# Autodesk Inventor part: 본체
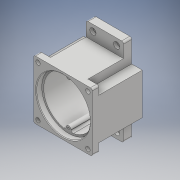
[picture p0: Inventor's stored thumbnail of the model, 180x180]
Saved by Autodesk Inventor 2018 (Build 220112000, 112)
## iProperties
Created: 2020-07
Part Number: 본체
Material: 일반
Document SubType Name: Modeling
Designer: Admin
Density: 1 g/cm^3
Appearance: 기본값
Author: Admin
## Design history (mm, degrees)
sketch "스케치1"
  geometry: L1 (65.8, 0)-(-65.8, 0) reference; L2 (0, -65.8)-(0, 65.8) reference; L3 (47, -47)-(-47, -47); L4 (-47, -47)-(-47, 47); L5 (-47, 47)-(47, 47); L6 (47, 47)-(47, -47); L7 (47, -47)-(-47, 47); L8 (-47, -47)-(47, 47); 1 further point
  constraints: 12 end point, 2 midpoint, 2 parallel, 1 horizontal, 1 perpendicular
  dimensions: "d0" = 94 distance of L4.end L5.end; "d1" = 94 distance of L3.end L4.end
extrude "돌출1" new body sketch "스케치1" distance "d2" = 10; taper "d3" = 0 deg
sketch "스케치2"
  geometry: L1 (-65.8, 0)-(65.8, 0) reference; L2 (0, 65.8)-(0, -65.8) reference; L3 (47, -33)-(-47, -33); L4 (-47, -33)-(-47, 33); L5 (-47, 33)-(47, 33); L6 (47, 33)-(47, -33); L7 (47, -33)-(-47, 33); L8 (-47, -33)-(47, 33); 1 further point
  constraints: 12 end point, 2 midpoint, 2 parallel, 1 horizontal, 1 perpendicular
  dimensions: "d4" = 94 distance of L4.end L5.end; "d5" = 66 distance of L3.end L4.end
extrude "돌출2" join sketch "스케치2" distance "d6" = 57; taper "d7" = 0 deg
sketch "스케치3"
  geometry: L1 (-47, -33)-(47, -33) reference; L2 (47, -33)-(47, 33) reference; L3 (47, 33)-(-47, 33) reference; L4 (-47, 33)-(-47, -33) reference; L5 (-65.8, 0)-(65.8, 0) reference; L6 (0, 98)-(0, -98) reference; L7 (30, -70)-(-30, -70); L8 (-30, -70)-(-30, 70); L9 (-30, 70)-(30, 70); L10 (30, 70)-(30, -70); L11 (30, -70)-(-30, 70); L12 (-30, -70)-(30, 70); L13 (-30, -70)-(30, -70); L14 (-30, 70)-(30, 70); L15 (47, -33)-(47, 33) reference; L16 (47, -33)-(47, 33); L17 (-47, -33)-(-47, 33); L18 (47, -33)-(-47, -33) reference; L19 (-47, -33)-(-30, -33); L20 (-30, -70)-(-30, -33); L21 (-47, 33)-(47, 33) reference; L22 (-47, 33)-(-30, 33); L23 (-30, 33)-(-30, 70); L24 (30, -70)-(30, -33); L25 (30, -33)-(47, -33); L26 (30, 33)-(47, 33); L27 (30, 33)-(30, 70); 1 further point
  constraints: 36 end point, 9 point on line, 7 collinear, 2 midpoint, 2 parallel, 1 horizontal, 1 perpendicular, 1 vertical
  dimensions: "d8" = 60 distance of L8.end L9.end; "d9" = 140 distance of L7.end L8.end
extrude "돌출3" join sketch "스케치3" distance "d10" = 13; taper "d11" = 0 deg
sketch "스케치4"
  geometry: L1 (-47, -33)-(-30, -33) reference; L2 (-30, -33)-(-30, -70) reference; L3 (-30, -70)-(30, -70) reference; L4 (30, -70)-(30, -33) reference; L5 (30, -33)-(47, -33) reference; L6 (47, -33)-(47, 33) reference; L7 (47, 33)-(30, 33) reference; L8 (30, 33)-(30, 70) reference; L9 (30, 70)-(-30, 70) reference; L10 (-30, 70)-(-30, 33) reference; L11 (-30, 33)-(-47, 33) reference; L12 (-47, 33)-(-47, -33) reference; L13 (-65.8, 0)-(65.8, 0) reference; L14 (0, 98)-(0, -98) reference; C1 r 27.5 at (-11, 0); 1 further point
  constraints: 1 centre point, 1 point on line
  dimensions: "d12" = 55 diameter of C1; "d13" = 11 distance of point (0, 0) C1.centre
extrude "돌출4" join sketch "스케치4" distance "d14" = 7; taper "d15" = 0 deg
sketch "스케치5"
  geometry: C1 r 27.5 at (0, 0) reference; C2 r 16 at (0, 0); 1 further point
  constraints: 1 centre point, 1 coincident
  dimensions: "d16" = 32 diameter of C2
extrude "돌출5" cut sketch "스케치5" distance "d17" = 8.3; taper "d18" = 0 deg
sketch "스케치6"
  geometry: C1 r 16 at (0, 0) reference; C2 r 12.5 at (0, 0); 1 further point
  constraints: 1 centre point, 1 coincident
  dimensions: "d19" = 25 diameter of C2
extrude "돌출6" cut sketch "스케치6" distance "d20" = 4.7; taper "d21" = 0 deg
sketch "스케치7"
  geometry: C1 r 12.5 at (0, 0) reference; C2 r 17.5 at (0, 0); 1 further point
  constraints: 1 centre point, 1 coincident
  dimensions: "d22" = 35 diameter of C2
extrude "돌출7" cut sketch "스케치7" distance "d23" = 10; taper "d24" = 0 deg
sketch "스케치8"
  geometry: L1 (-47, -47)-(47, -47) reference; L2 (47, -47)-(47, 47) reference; L3 (47, 47)-(-47, 47) reference; L4 (-47, 47)-(-47, -47) reference; L5 (-65.8, 0)-(65.8, 0) reference; L6 (0, -98)-(0, 98) reference; C1 r 43 at (0, 0); 1 further point
  constraints: 1 centre point, 1 coincident
  dimensions: "d25" = 86 diameter of C1
extrude "돌출8" cut sketch "스케치8" distance "d26" = 9; taper "d27" = 0 deg
sketch "스케치9"
  geometry: L1 (-65.8, 0)-(65.8, 0) reference; L2 (0, -98)-(0, 98) reference; C1 r 43 at (0, 0) reference; C2 r 40 at (0, 0); 1 further point
  constraints: 1 centre point, 1 coincident
  dimensions: "d28" = 80 diameter of C2
sketch "스케치10"
  geometry: L1 (-47, 47)-(47, 47) reference; L2 (-47, -47)-(-47, 47) reference; L3 (47, 47)-(47, -47) reference; L4 (47, -47)-(-47, -47) reference; L5 (-65.8, 0)-(65.8, 0) reference; L6 (0, 98)-(0, -98) reference; L7 (-30, 47)-(30, 47); L8 (-30, 47)-(-30, 33); L9 (-30, 33)-(30, 33); L10 (30, 33)-(30, 47); L11 (-30, -47)-(-30, -33); L12 (-30, -33)-(30, -33); L13 (-30, -47)-(30, -47); L14 (30, -33)-(30, -47); 1 further point
  constraints: 16 end point, 5 symmetric about line, 3 perpendicular, 2 point on line
  dimensions: "d29" = 60 distance of L7.start L7.end; "d30" = 14 distance of L7.start L8.end
extrude "돌출9" join sketch "스케치10" stored distance "d31" = 55; taper "d32" = 0 deg
extrude "돌출10" cut sketch "스케치9" distance "d33" = 55; taper "d34" = 0 deg
sketch "스케치11"
  geometry: L1 (-65.8, 0)-(65.8, 0) reference; L2 (0, -98)-(0, 98) reference; C1 r 17.5 at (-11, 0) reference; C2 r 17.5 at (-11, 0) reference; C3 r 40 at (0, 0); A1 r 21 centre (-11, 0) between (7.984, 8.978) and (7.984, -8.978); A2 r 15 centre (20, 0) between (7.984, 8.978) and (7.984, -8.978); A3 r 21 centre (-11, 0) between (7.984, 8.978) and (7.984, -8.978); A4 r 15 centre (20, 0) between (7.984, -8.978) and (7.984, 8.978); 1 further point
  constraints: 8 point on circle, 5 centre point, 4 coincident, 1 point on line
  dimensions: "d35" = 42 diameter of A1; "d36" = 30 diameter of A2; "d37" = 20 distance from line of A2.centre L2; "d38" = 80 diameter of C3
extrude "돌출11" cut sketch "스케치11" distance "d39" = 7; taper "d40" = 0 deg
sketch "스케치12"
  geometry: L1 (-65.8, 0)-(65.8, 0) reference; L2 (0, -98)-(0, 98) reference; C1 r 17.5 at (-11, 0) reference; C2 r 11 at (20, 0); A1 r 15 centre (20, 0) between (7.984, -8.978) and (7.984, 8.978) reference; A2 r 21 centre (-11, 0) between (7.984, 8.978) and (7.984, -8.978) reference; 1 further point
  constraints: 1 centre point, 1 coincident
  dimensions: "d41" = 22 diameter of C2
extrude "돌출12" cut sketch "스케치12" distance "d42" = 7; taper "d43" = 0 deg
sketch "스케치13"
  geometry: C1 r 11 at (0, 0) reference; C2 r 9.5 at (0, 0); 1 further point
  constraints: 1 centre point, 1 coincident
  dimensions: "d44" = 19 diameter of C2
extrude "돌출13" cut sketch "스케치13" distance "d45" = 3; taper "d46" = 0 deg
sketch "스케치14"
  geometry: L1 (-65.8, 0)-(65.8, 0) reference; L2 (0, -98)-(0, 98) reference; L3 (-3.994, 35.778)-(-3.994, 41.932); L4 (3.994, 35.778)-(3.994, 41.932); L5 (3.994, 41.932)-(-3.994, 41.932); L6 (-3.994, 35.778)-(-3.994, 42.814); L7 (3.994, 35.778)-(3.994, 42.814); L8 (-3.994, -35.778)-(-3.994, -42.814); L9 (3.994, -35.778)-(3.994, -42.814); C1 r 40 at (0, 0) reference; A1 r 43 centre (0, 0) between (-3.994, 42.814) and (3.994, 42.814) reference; A2 r 36 centre (0, 0) between (0, 36) and (-3.994, 35.778); A3 r 4 centre (0, 36) between (-3.994, 35.778) and (3.994, 35.778); A4 r 4 centre (0, 36) between (-3.994, 35.778) and (3.994, 35.778); A5 r 43 centre (0, 0) between (3.994, 42.814) and (-3.994, 42.814); A6 r 43 centre (0, 0) between (-3.994, -42.814) and (3.994, -42.814); A7 r 4 centre (0, -36) between (3.994, -35.778) and (-3.994, -35.778); 1 further point
  constraints: 15 point on circle, 14 end point, 6 centre point, 5 symmetric about line, 3 coincident, 3 point on line, 2 vertical, 1 perpendicular, 2 other
  dimensions: "d47" = 72 diameter of A2; "d48" = 8 diameter of A3
extrude "돌출14" join sketch "스케치14" stored distance "d49" = 3; taper "d50" = 0 deg
sketch "스케치15"
  geometry: L1 (-47, -47)-(47, -47) reference; L2 (47, -47)-(47, 47) reference; L3 (47, 47)-(-47, 47) reference; L4 (-47, 47)-(-47, -47) reference; L5 (-65.8, 0)-(65.8, 0) reference; L6 (0, -98)-(0, 98) reference; L7 (40, -40)-(-40, -40); L8 (-40, -40)-(-40, 40); L9 (-40, 40)-(40, 40); L10 (40, 40)-(40, -40); L11 (40, -40)-(-40, 40); L12 (-40, -40)-(40, 40); C1 r 43 at (0, 0) reference; 5 further points
  constraints: 12 end point, 4 coincident, 2 midpoint, 2 parallel, 1 horizontal, 1 perpendicular
  dimensions: "d51" = 80 distance of L8.end L9.end; "d52" = 80 distance of L7.end L8.end
hole "구멍1" sketch "스케치15" at (-40, -40), (-40, 40), (40, 40), (40, -40) diameter "d53" = 7; stored, may be unused: countersink angle "d57" = 90 deg, drill point angle "d59" = 118 deg; dims "d54" = 6, "d55" = 4, "d56" = 2, "d58" = 10
sketch "스케치16"
  geometry: L1 (-65.8, 0)-(65.8, 0) reference; L2 (0, -98)-(0, 98) reference; L3 (19, -60)-(-19, -60); L4 (-19, -60)-(-19, 60); L5 (-19, 60)-(19, 60); L6 (19, 60)-(19, -60); L7 (19, -60)-(-19, 60); L8 (-19, -60)-(19, 60); 5 further points
  constraints: 12 end point, 4 coincident, 2 midpoint, 2 parallel, 1 horizontal, 1 perpendicular
  dimensions: "d60" = 38 distance of L4.end L5.end; "d61" = 120 distance of L3.end L4.end
hole "구멍2" sketch "스케치16" at (-19, 60), (19, 60), (-19, -60), (19, -60) diameter "d62" = 4.5; stored, may be unused: countersink angle "d66" = 90 deg, drill point angle "d68" = 118 deg; dims "d63" = 6, "d64" = 10, "d65" = 5, "d67" = 13
sketch "스케치17"
  geometry: L1 (94, 0)-(0, 0) reference; L2 (94, 0)-(94, 10) reference; L3 (80, 10)-(94, 10) reference; L4 (80, 10)-(80, 80) reference; L5 (14, 80)-(80, 80) reference; L6 (14, 10)-(14, 80) reference; L7 (0, 10)-(14, 10) reference; L8 (0, 0)-(0, 10) reference; L9 (47, -17.4)-(47, 104.4) reference; L10 (-51, 0)-(145, 0) reference; 2 further points
  constraints: 1 other
  dimensions: "d69" = 40 distance from line of L1 point (47, 40)
feature "엠보싱1" sketch "스케치17" dims "d70" = 0.5, "d71" = 0
sketch "스케치18"
  geometry: L1 (3.994, -39.8)-(3.994, -35.778) reference; L2 (-3.994, -35.778)-(-3.994, -39.8) reference; L3 (-3.994, 39.8)-(-3.994, 35.778) reference; L4 (3.994, 35.778)-(3.994, 39.8) reference; C1 r 43 at (0, 0) reference; A1 r 40 centre (0, 0) between (3.994, -39.8) and (3.994, 39.8) reference; A2 r 4 centre (0, -36) between (3.994, -35.778) and (-3.994, -35.778) reference; A3 r 40 centre (0, 0) between (-3.994, 39.8) and (-3.994, -39.8) reference; A4 r 4 centre (0, 36) between (-3.994, 35.778) and (3.994, 35.778) reference; 3 further points
  constraints: 2 coincident
hole "구멍3" sketch "스케치18" at (0, -36), (0, 36) diameter "d72" = 3.242; stored, may be unused: countersink angle "d76" = 90 deg, drill point angle "d78" = 118 deg; dims "d73" = 7, "d74" = 10, "d75" = 5, "d77" = 9
chamfer "모따기1" distance "d79" = 0.8; stored, may be unused: second distance "d80" = 2, angle "d81" = 30 deg
chamfer "모따기2" distance "d82" = 1; stored, may be unused: second distance "d83" = 2, angle "d84" = 45 deg
chamfer "모따기3" distance "d85" = 1; stored, may be unused: second distance "d86" = 2, angle "d87" = 45 deg
fillet "모깎기1" dims "d88" = 3
node "솔리드1"
node "투영된 루프1"
node "투영된 루프2"
node "투영된 루프3"
node "투영된 루프4"
node "투영된 루프5"
node "투영된 루프6"
node "투영된 루프7"
node "투영된 루프8"
node "투영된 루프9"
node "투영된 루프10"
node "투영된 루프11"
node "투영된 루프12"
